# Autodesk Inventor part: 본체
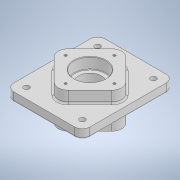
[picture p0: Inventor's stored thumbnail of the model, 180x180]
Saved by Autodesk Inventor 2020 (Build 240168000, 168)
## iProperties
Created: 2021-07
Part Number: 본체
Material: 일반
Document SubType Name: Modeling
Designer: Owner
Density: 1 g/cm^3
Appearance: 기본값
Mass: 807.976 g
Surface Area: 961.758 cm^2
Volume: 807.976 cm^3
Author: Owner
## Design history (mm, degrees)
sketch "스케치1"
  geometry: L1 (-75, 90)-(75, 90); L2 (75, 90)-(75, -90); L3 (75, -90)-(-75, -90); L4 (-75, -90)-(-75, 90); L5 (-75, 90)-(75, -90); L6 (75, 90)-(-75, -90); 1 further point
  constraints: 12 end point, 2 midpoint, 2 parallel, 1 horizontal, 1 perpendicular
  dimensions: "d0" = 150 distance of L2.end L3.end; "d1" = 180 distance of L1.end L2.end
extrude "돌출1" new body sketch "스케치1" stored distance "d2" = 18; taper "d3" = 0 deg
sketch "스케치2"
  geometry: L1 (-70.711, 0)-(0, 70.711); L2 (0, 70.711)-(70.711, 0); L3 (70.711, 0)-(0, -70.711); L4 (0, -70.711)-(-70.711, 0); L5 (-70.711, 0)-(70.711, 0); L6 (0, 70.711)-(0, -70.711); 1 further point
  constraints: 12 end point, 2 midpoint, 2 parallel, 1 perpendicular, 1 vertical
  dimensions: "d4" = 100 distance of L1.start L1.end; "d5" = 100 distance of L3.end L1.start
extrude "돌출2" join sketch "스케치2" distance "d6" = 23; taper "d7" = 0 deg
node "작업 평면1"
sketch "스케치3"
  geometry: L1 (70.711, 0)-(0, -70.711); L2 (0, -70.711)-(-70.711, 0); L3 (-70.711, 0)-(0, 70.711); L4 (0, 70.711)-(70.711, 0); L5 (70.711, 0)-(-70.711, 0); L6 (0, -70.711)-(0, 70.711); 1 further point
  constraints: 12 end point, 2 midpoint, 2 parallel, 1 horizontal, 1 perpendicular
  dimensions: "d9" = 100 distance of L2.end L3.end; "d10" = 100 distance of L1.end L2.end
extrude "돌출3" join sketch "스케치3" stored distance "d11" = 23; taper "d12" = 0 deg
fillet "모깎기1" dims "d13" = 20
fillet "모깎기2" dims "d14" = 15
sketch "스케치4"
  geometry: C1 r 11 at (-55, 70); C2 r 11 at (55, 70); C3 r 11 at (55, -70); C4 r 11 at (-55, -70); 1 further point
  constraints: 4 centre point, 3 equal radius, 2 horizontal alignment, 2 vertical alignment
  dimensions: "d15" = 110 distance of C1.centre C2.centre; "d16" = 140 distance of C3.centre C2.centre; "d17" = 70 vertical distance of point (0, 0) C2.centre; "d18" = 55 horizontal distance of point (0, 0) C1.centre; "d19" = 22 diameter of C2; "d20" = 22 diameter of C4 (derived)
extrude "돌출4" join sketch "스케치4" distance "d21" = 5; taper "d22" = 0 deg
sketch "스케치5"
  geometry: C1 r 11 at (0, 0) reference; 2 further points
  constraints: 1 coincident
hole "구멍1" sketch "스케치5" at (0, 0) diameter "d23" = 11; stored, may be unused: countersink angle "d27" = 90 deg, drill point angle "d29" = 118 deg; dims "d24" = 6, "d25" = 4, "d26" = 2, "d28" = 8
sketch "스케치6"
  geometry: 2 further points
  constraints: 1 horizontal alignment
  dimensions: "d30" = 48 distance of point (48, 0) point (0, 0)
hole "구멍2" sketch "스케치6" at (48, 0) diameter "d31" = 4.917; stored, may be unused: countersink angle "d35" = 90 deg, drill point angle "d37" = 118 deg; dims "d32" = 10, "d33" = 4, "d34" = 2, "d36" = 13
sketch "스케치7"
  geometry: 2 further points
  constraints: 1 coincident
hole "구멍3" sketch "스케치7" at (0, 0) diameter "d41" = 45; stored, may be unused: countersink angle "d45" = 90 deg, drill point angle "d47" = 118 deg; dims "d42" = 10, "d43" = 62, "d44" = 22, "d46" = 13
fillet "모깎기3" dims "d48" = 1
chamfer "모따기1" distance "d49" = 1; stored, may be unused: second distance "d50" = 2, angle "d51" = 45 deg
fillet "모깎기4" dims "d52" = 3
fillet "모깎기5" dims "d53" = 3
fillet "모깎기6" dims "d54" = 3
sketch "스케치8"
  geometry: 2 further points
  constraints: 1 vertical alignment
  dimensions: "d55" = 48 distance of point (0, 0) point (0, -48)
hole "구멍4" sketch "스케치8" at (0, -48) diameter "d56" = 4.917; stored, may be unused: countersink angle "d60" = 90 deg, drill point angle "d62" = 118 deg; dims "d57" = 10, "d58" = 62, "d59" = 22, "d61" = 13
sketch "스케치9"
  geometry: L1 (60, 90)-(-60, 90) reference; 2 further points
  constraints: 1 vertical alignment, 1 other
  dimensions: "d66" = 15 distance from line of L1 point (0, 75)
feature "엠보싱1" sketch "스케치9" dims "d0" = 150, "d1" = 180, "d67" = 0.5, "d68" = 0
sketch "스케치10"
  geometry: C1 r 22.5 at (0, 0) reference; 2 further points
  constraints: 1 coincident
hole "구멍5" sketch "스케치10" at (0, 0) diameter "d69" = 62; stored, may be unused: countersink angle "d73" = 90 deg, drill point angle "d75" = 0 deg; dims "d70" = 10, "d71" = 62, "d72" = 22, "d74" = 22
chamfer "모따기2" distance "d79" = 1; stored, may be unused: second distance "d80" = 2, angle "d81" = 45 deg
fillet "모깎기7" dims "d85" = 1
node "솔리드1"
mirror "미러1"
mirror "미러2"
pattern_circular "원형 패턴1" dims angle "d39" = 360 deg
pattern_circular "원형 패턴3" dims angle "d77" = 360 deg
feature "A9D066F2-1C7D-4E18-AEED-F7BC21143FA4" dims "d23" = 11, "d24" = 6, "d25" = 4, "d26" = 2, "d27" = 90 deg, "d28" = 8, "d29" = 118 deg
